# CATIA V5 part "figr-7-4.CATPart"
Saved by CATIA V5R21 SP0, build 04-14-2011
Part number: Part1
Bounding box of the stored display mesh (mm): x -20 to 20, y -95 to 0, z 0 to 40
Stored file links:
  D:\CATIA V5R21 E-RESOURCES\CATIA-V5R21\catia-v5r21-prt\c07-catia-v5r20-prt\c07-catia-v5r21-figr-7-4.CATPart
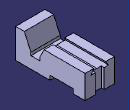
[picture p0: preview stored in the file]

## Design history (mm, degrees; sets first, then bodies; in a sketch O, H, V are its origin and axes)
Body1 (main body)
  Sketch1 on yz-plane, origin (0, 0, 0), H (0, 1, 0), V (0, 0, 1)
    line L1 (0, 0) -> (-16, 0)
    line L2 (-16, 0) -> (-16, 6)
    line L3 (-16, 6) -> (-48, 6)
    line L4 (-48, 6) -> (-48, 0)
    point P4 (-48, 0)
    line L5 (-48, 0) -> (-95, 0)
    line L6 (-95, 0) -> (-95, 40)
    line L7 (-95, 40) -> (-83, 40)
    line L8 (-83, 40) -> (-74, 20)
    line L9 (-74, 20) -> (-74, 16)
    line L10 (-74, 16) -> (-62, 16)
    line L11 (-62, 16) -> (-62, 20)
    line L12 (-62, 20) -> (-56, 32)
    line L13 (-56, 32) -> (0, 32)
    line L14 (0, 32) -> (0, 0)
    length L1 = 16
    length L3 = 32
    length L13 = 56
    distance L14 L6 = 95
    length L14 = 32
    length L6 = 40
    length L12 H = 6
    length L10 = 12
    length L7 = 12
    length L9 = 4
    length L2 = 6
    distance L10 L5 = 16
    length L12 V = 12
    horizontal: L1 H, L3 H, L5 H, L7 H, L10 H, L13 H
    vertical: L2 V, L4 V, L6 V, L9 V, L11 V, L14 V
    coincidence: P4 H
  Pad1: profile Sketch1, direction (1, 0, 0), length 20, mirrored extent
  Sketch2 on face of Pad1, origin (0, 0, 0), H (-1, 0, 0), V (0, 0, 1)
    axis line L1 (0, 0) -> (0, 40.9766)
    point P2 (0, 32)
    line L2 (0, 32) -> (-8, 32)
    point P3 (-8, 32)
    line L3 (-8, 32) -> (-12, 26)
    point P4 (-12, 26)
    line L4 (-12, 26) -> (0, 26)
    point P5 (0, 26)
    reference projected line E1 (-20, 32) -> (20, 32) from edge [face of Pad1 | face of Pad1]
    point P6 (0, 32)
    point P7 (8, 32)
    point P8 (12, 26)
    point P9 (0, 26)
    line L5 (0, 32) -> (8, 32)
    line L6 (8, 32) -> (12, 26)
    line L7 (12, 26) -> (0, 26)
    reference projected line E2 (-20, 0) -> (-20, 32) from edge [face of Pad1 | face of Pad1]
    reference projected line E3 (-20, 20) -> (-20, 40) from edge [face of Pad1 | face of Pad1]
    distance P4 E2 = 8
    length L3 V = 6
    distance P3 E3 = 12
    vertical: L1 V
    coincidence: P2 L1, P5 L1, L2 E1, P2 P6, P5 P9
    horizontal: L2 H, L4 H
    symmetry: P2 P6 L1, P3 P7 L1, P4 P8 L1, P5 P9 L1, L2 L5 L1, L3 L6 L1, L4 L7 L1
  Pocket1: profile Sketch2, direction (0, -1, 0), through (limit type 6)
  Sketch3 on face of Pad1, origin (0, 0, 0), H (-1, 0, 0), V (0, 0, 1)
    line L1 (-6, 0) -> (6, 0)
    line L2 (6, 0) -> (6, 26)
    line L3 (6, 26) -> (-6, 26)
    line L4 (-6, 26) -> (-6, 0)
    reference projected line E1 (-12, 26) -> (0, 26) from edge [face of Pad1 | face of Pocket1]
    length L1 = 12
    horizontal: L1 H, L3 H
    vertical: L2 V, L4 V
    midpoint: O L1
    coincidence: L3 E1
  Pocket2: profile Sketch3, direction (0, -1, 0), length 4
  Sketch4 "Sketch.4" on face of Pad1, origin (0, 0, 40), H (1, 0, 0), V (0, 1, 0)
    line L1 (-12.5, -95) -> (12.5, -95)
    line L2 (12.5, -95) -> (12.5, -92)
    line L3 (12.5, -92) -> (-12.5, -92)
    line L4 (-12.5, -92) -> (-12.5, -95)
    reference projected line E1 (-20, -95) -> (20, -95) from edge [face of Pad1 | face of Pad1]
    axis line L5 (0, 0) -> (0, -95)
    point P5 (0, -95)
    length L1 = 25
    length L2 = 3
    horizontal: L1 H, L3 H
    vertical: L2 V, L4 V, L5 V
    coincidence: L1 E1
    midpoint: P5 L1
